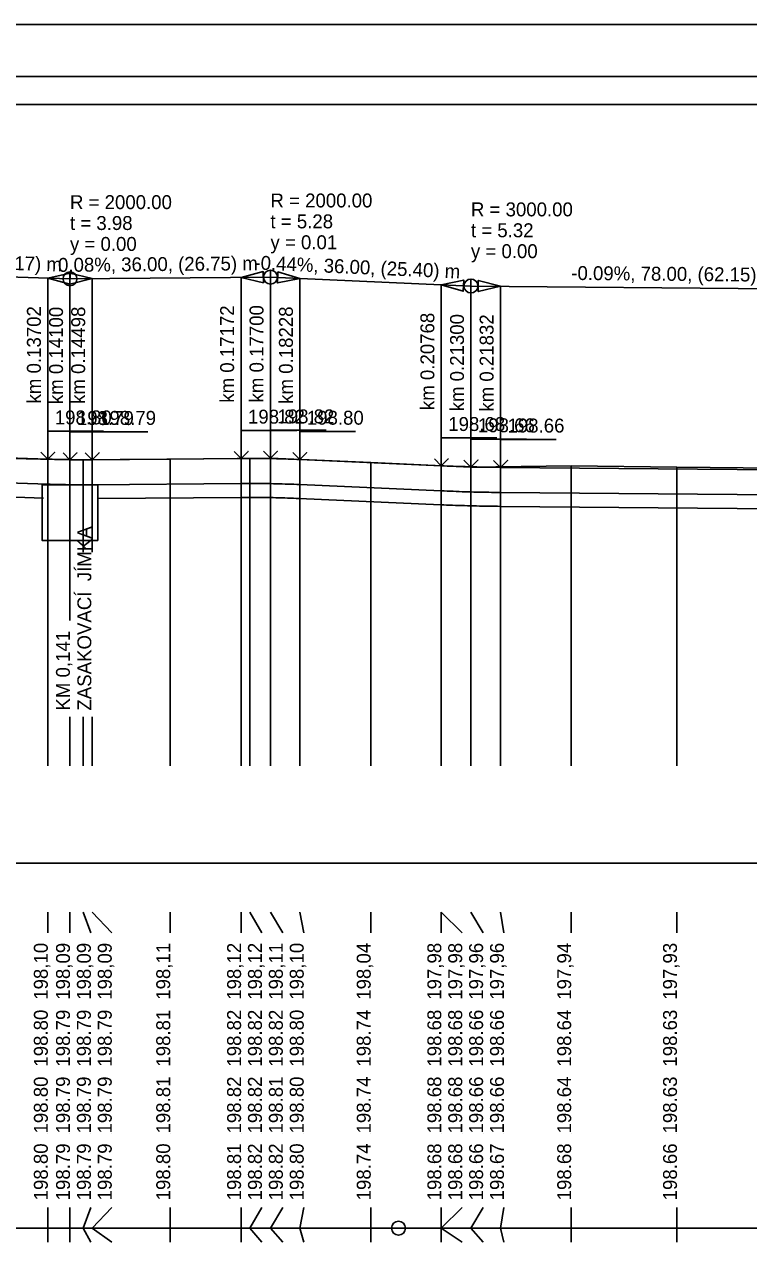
# Model space of a CAD drawing. Extents: x -51 to 53, y -74 to 15.
# Drawn here: x -25.16 to -12.15, y -6.73 to 15.15 of the extents above; entities that cross this region are included whole.
import ezdxf

# ---------------------------------------------------------------- set-up
doc = ezdxf.new("R2010")
doc.units = 0
for name, color, linetype in [('Implicitní', 7, 'Continuous'), ('KONSTRUKCE_L', 7, 'Continuous'), ('KOTY_L', 7, 'Continuous'), ('KOTY_N', 7, 'Continuous'), ('KOTY_S', 7, 'Continuous'), ('KOTY_T', 7, 'Continuous'), ('KOTY_VP', 7, 'Continuous'), ('Nová vrstva (0)', 7, 'Continuous'), ('PR_SKLON_L', 7, 'Continuous'), ('ROVINA_L', 7, 'Continuous'), ('ROVINA_O', 7, 'Continuous'), ('SKLON_POMERY', 7, 'Continuous'), ('TABULKY_L', 7, 'Continuous'), ('TEREN_L', 7, 'Continuous'), ('V_POLYGON', 7, 'Continuous'), ('V_POLYGON_ZO', 7, 'Continuous')]:
    doc.layers.add(name, color=color, linetype=linetype)

msp = doc.modelspace()

# ---------------------------------------------------------------- linework, layer by layer
at = {"layer": 'Implicitní'}
msp.add_lwpolyline([(-51.392, 15.154), (53.079, 15.154), (53.079, -14.546), (-51.392, -14.546)], close=True, dxfattribs=at)
at = {"layer": 'KONSTRUKCE_L'}
for p, q in [((-26.854, 6.968), (-24.738, 6.901)), ((-24.738, 6.901), (-24.698, 6.9)), ((-24.698, 6.9), (-24.658, 6.899)), ((-24.658, 6.899), (-24.618, 6.898)), ((-24.618, 6.898), (-24.579, 6.897)), ((-24.579, 6.897), (-24.539, 6.896)), ((-24.539, 6.896), (-24.499, 6.895)), ((-24.499, 6.895), (-24.459, 6.895)), ((-24.459, 6.895), (-24.42, 6.894)), ((-24.42, 6.894), (-24.38, 6.893)), ((-24.38, 6.893), (-24.34, 6.893)), ((-24.34, 6.893), (-24.3, 6.892)), ((-24.3, 6.892), (-24.26, 6.892)), ((-24.26, 6.892), (-24.221, 6.892)), ((-24.221, 6.892), (-24.181, 6.892)), ((-24.181, 6.892), (-24.141, 6.891)), ((-24.141, 6.891), (-24.101, 6.891)), ((-24.101, 6.891), (-24.062, 6.891)), ((-24.062, 6.891), (-24.022, 6.892)), ((-24.022, 6.892), (-23.982, 6.892)), ((-23.982, 6.892), (-23.942, 6.892)), ((-23.942, 6.892), (-21.268, 6.914)), ((-21.268, 6.914), (-21.215, 6.915)), ((-21.215, 6.915), (-21.162, 6.915)), ((-21.162, 6.915), (-21.109, 6.915)), ((-21.109, 6.915), (-21.057, 6.915)), ((-21.057, 6.915), (-21.004, 6.915)), ((-21.004, 6.915), (-20.951, 6.915)), ((-20.951, 6.915), (-20.898, 6.914)), ((-20.898, 6.914), (-20.846, 6.913)), ((-20.846, 6.913), (-20.793, 6.913)), ((-20.793, 6.913), (-20.74, 6.912)), ((-20.74, 6.912), (-20.687, 6.911)), ((-20.687, 6.911), (-20.634, 6.91)), ((-20.634, 6.91), (-20.582, 6.908)), ((-20.582, 6.908), (-20.529, 6.907)), ((-20.529, 6.907), (-20.476, 6.905)), ((-20.476, 6.905), (-20.423, 6.904)), ((-20.423, 6.904), (-20.371, 6.902)), ((-20.371, 6.902), (-20.318, 6.9)), ((-20.318, 6.9), (-20.265, 6.898)), ((-20.265, 6.898), (-20.212, 6.895)), ((-20.212, 6.895), (-17.672, 6.782)), ((-17.672, 6.782), (-17.619, 6.78)), ((-17.619, 6.78), (-17.566, 6.778)), ((-17.566, 6.778), (-17.512, 6.776)), ((-17.512, 6.776), (-17.459, 6.774)), ((-17.459, 6.774), (-17.406, 6.772)), ((-17.406, 6.772), (-17.353, 6.77)), ((-17.353, 6.77), (-17.3, 6.768)), ((-17.3, 6.768), (-17.246, 6.767)), ((-17.246, 6.767), (-17.193, 6.765)), ((-17.193, 6.765), (-17.14, 6.764)), ((-17.14, 6.764), (-17.087, 6.762)), ((-17.087, 6.762), (-17.034, 6.761)), ((-17.034, 6.761), (-16.98, 6.76)), ((-16.98, 6.76), (-16.927, 6.759)), ((-16.927, 6.759), (-16.874, 6.758)), ((-16.874, 6.758), (-16.821, 6.757)), ((-16.821, 6.757), (-16.768, 6.756)), ((-16.768, 6.756), (-16.714, 6.755)), ((-16.714, 6.755), (-16.661, 6.755)), ((-16.661, 6.755), (-16.608, 6.754)), ((-16.608, 6.754), (-10.393, 6.698))]:
    msp.add_line(p, q, dxfattribs=at)
at = {"layer": 'KOTY_L'}
for p, q in [((-24.738, 1.849), (-24.738, 7.348)), ((-24.34, 4.456), (-24.34, 7.339)), ((-24.101, 5.684), (-24.101, 7.34)), ((-23.942, 5.684), (-23.942, 7.341)), ((-22.54, 1.849), (-22.54, 7.349)), ((-21.268, 1.849), (-21.268, 7.363)), ((-21.109, 1.849), (-21.109, 7.365)), ((-20.74, 1.849), (-20.74, 7.369)), ((-20.212, 1.849), (-20.212, 7.345)), ((-18.94, 1.849), (-18.94, 7.289)), ((-17.672, 1.849), (-17.672, 7.232)), ((-17.672, 1.849), (-17.672, 7.232)), ((-15.34, 1.849), (-15.34, 7.229)), ((-17.14, 1.849), (-17.14, 7.209)), ((-16.608, 1.849), (-16.608, 7.215)), ((-13.44, 1.849), (-13.44, 7.209)), ((-24.34, 1.849), (-24.34, 2.725)), ((-24.101, 1.849), (-24.101, 2.725)), ((-23.942, 1.849), (-23.942, 2.725)), ((-24.738, -1.151), (-24.738, -0.776)), ((-24.34, -1.151), (-24.34, -0.776)), ((-23.965, -1.151), (-24.101, -0.776)), ((-23.59, -1.151), (-23.942, -0.776)), ((-22.54, -1.151), (-22.54, -0.776)), ((-21.268, -1.151), (-21.268, -0.776)), ((-20.893, -1.151), (-21.109, -0.776)), ((-20.518, -1.151), (-20.74, -0.776)), ((-20.143, -1.151), (-20.212, -0.776)), ((-18.94, -1.151), (-18.94, -0.776)), ((-17.672, -1.151), (-17.672, -0.776)), ((-17.297, -1.151), (-17.672, -0.776)), ((-16.922, -1.151), (-17.14, -0.776)), ((-16.547, -1.151), (-16.608, -0.776)), ((-15.34, -1.151), (-15.34, -0.776)), ((-13.44, -1.151), (-13.44, -0.776)), ((-24.738, -4.751), (-24.738, -4.751)), ((-24.34, -4.751), (-24.34, -4.751)), ((-23.965, -4.751), (-23.965, -4.751)), ((-23.59, -4.751), (-23.59, -4.751)), ((-22.54, -4.751), (-22.54, -4.751)), ((-21.268, -4.751), (-21.268, -4.751)), ((-20.893, -4.751), (-20.893, -4.751)), ((-20.518, -4.751), (-20.518, -4.751)), ((-20.143, -4.751), (-20.143, -4.751)), ((-18.94, -4.751), (-18.94, -4.751)), ((-17.672, -4.751), (-17.672, -4.751)), ((-17.297, -4.751), (-17.297, -4.751)), ((-16.922, -4.751), (-16.922, -4.751)), ((-16.547, -4.751), (-16.547, -4.751)), ((-15.34, -4.751), (-15.34, -4.751)), ((-13.44, -4.751), (-13.44, -4.751)), ((-24.738, -6.451), (-24.738, -6.076)), ((-24.34, -6.451), (-24.34, -6.076)), ((-24.101, -6.451), (-23.965, -6.076)), ((-23.942, -6.451), (-23.59, -6.076)), ((-22.54, -6.451), (-22.54, -6.076)), ((-21.268, -6.451), (-21.268, -6.076)), ((-21.109, -6.451), (-20.893, -6.076)), ((-20.74, -6.451), (-20.518, -6.076)), ((-20.212, -6.451), (-20.143, -6.076)), ((-18.94, -6.451), (-18.94, -6.076)), ((-17.672, -6.451), (-17.672, -6.076)), ((-17.672, -6.451), (-17.297, -6.076)), ((-17.14, -6.451), (-16.922, -6.076)), ((-16.608, -6.451), (-16.547, -6.076)), ((-15.34, -6.451), (-15.34, -6.076)), ((-13.44, -6.451), (-13.44, -6.076))]:
    msp.add_line(p, q, dxfattribs=at)
at = {"layer": 'KOTY_S'}
for p, q in [((-24.738, -6.701), (-24.738, -6.451)), ((-24.34, -6.701), (-24.34, -6.451)), ((-23.965, -6.701), (-24.101, -6.451)), ((-23.59, -6.701), (-23.942, -6.451)), ((-22.54, -6.701), (-22.54, -6.451)), ((-21.268, -6.701), (-21.268, -6.451)), ((-20.893, -6.701), (-21.109, -6.451)), ((-20.518, -6.701), (-20.74, -6.451)), ((-20.143, -6.701), (-20.212, -6.451)), ((-18.94, -6.701), (-18.94, -6.451)), ((-17.672, -6.701), (-17.672, -6.451)), ((-17.297, -6.701), (-17.672, -6.451)), ((-16.922, -6.701), (-17.14, -6.451)), ((-16.547, -6.701), (-16.608, -6.451)), ((-15.34, -6.701), (-15.34, -6.451)), ((-13.44, -6.701), (-13.44, -6.451))]:
    msp.add_line(p, q, dxfattribs=at)
at = {"layer": 'Nová vrstva (0)'}
for p, q in [((-26.862, 6.718), (-24.816, 6.654)), ((-23.842, 6.643), (-21.266, 6.664)), ((-21.266, 6.664), (-21.213, 6.665)), ((-21.214, 6.665), (-21.161, 6.665)), ((-21.162, 6.665), (-21.109, 6.665)), ((-21.11, 6.665), (-21.057, 6.665)), ((-21.058, 6.665), (-21.005, 6.665)), ((-21.005, 6.665), (-20.953, 6.665)), ((-20.953, 6.665), (-20.901, 6.664)), ((-20.901, 6.664), (-20.848, 6.663)), ((-20.849, 6.663), (-20.796, 6.663)), ((-20.797, 6.663), (-20.744, 6.662)), ((-20.745, 6.662), (-20.692, 6.661)), ((-20.693, 6.661), (-20.64, 6.66)), ((-20.641, 6.66), (-20.588, 6.658)), ((-20.588, 6.658), (-20.536, 6.657)), ((-20.536, 6.657), (-20.484, 6.655)), ((-20.484, 6.655), (-20.431, 6.654)), ((-20.432, 6.654), (-20.379, 6.652)), ((-20.38, 6.652), (-20.327, 6.65)), ((-20.328, 6.65), (-20.275, 6.648)), ((-20.276, 6.648), (-20.223, 6.646)), ((-20.223, 6.646), (-17.683, 6.533)), ((-17.683, 6.533), (-17.63, 6.53)), ((-17.629, 6.53), (-17.576, 6.528)), ((-17.576, 6.528), (-17.522, 6.526)), ((-17.522, 6.526), (-17.469, 6.524)), ((-17.468, 6.524), (-17.415, 6.522)), ((-17.415, 6.522), (-17.361, 6.52)), ((-17.361, 6.52), (-17.308, 6.518)), ((-17.307, 6.518), (-17.254, 6.517)), ((-17.254, 6.517), (-17.201, 6.515)), ((-17.2, 6.515), (-17.147, 6.514)), ((-17.146, 6.514), (-17.093, 6.512)), ((-17.093, 6.512), (-17.04, 6.511)), ((-17.039, 6.511), (-16.986, 6.51)), ((-16.986, 6.51), (-16.932, 6.509)), ((-16.932, 6.509), (-16.879, 6.508)), ((-16.878, 6.508), (-16.825, 6.507)), ((-16.825, 6.507), (-16.771, 6.506)), ((-16.771, 6.506), (-16.718, 6.505)), ((-16.717, 6.505), (-16.664, 6.505)), ((-16.664, 6.505), (-16.61, 6.504)), ((-16.61, 6.504), (-10.395, 6.448))]:
    msp.add_line(p, q, dxfattribs=at)
msp.add_lwpolyline([(-24.84, 6.892), (-23.84, 6.892), (-23.84, 5.892), (-24.84, 5.892)], close=True, dxfattribs=at)
at = {"layer": 'PR_SKLON_L'}
msp.add_line((-38.44, 0.099), (-11.54, 0.099), dxfattribs=at)
at = {"layer": 'ROVINA_L'}
msp.add_line((-38.44, -6.451), (50.86, -6.451), dxfattribs=at)
at = {"layer": 'ROVINA_O'}
msp.add_circle((-18.44, -6.451), 0.125, dxfattribs=at)
at = {"layer": 'SKLON_POMERY'}
for p, q in [((-20.74, 10.619), (-20.74, 10.744)), ((-27.84, 10.699), (-24.34, 10.589)), ((-24.738, 7.351), (-24.738, 10.601)), ((-24.34, 10.589), (-24.34, 10.714)), ((-24.34, 10.589), (-20.74, 10.619)), ((-24.34, 7.339), (-24.34, 10.589)), ((-23.942, 7.342), (-23.942, 10.592)), ((-21.268, 7.364), (-21.268, 10.614)), ((-20.74, 7.369), (-20.74, 10.619)), ((-20.74, 10.619), (-17.14, 10.459)), ((-20.212, 7.345), (-20.212, 10.595)), ((-17.14, 10.459), (-17.14, 10.584)), ((-17.672, 7.232), (-17.672, 10.482)), ((-17.14, 7.209), (-17.14, 10.459)), ((-17.14, 10.459), (-9.34, 10.389)), ((-16.608, 7.204), (-16.608, 10.454))]:
    msp.add_line(p, q, dxfattribs=at)
for points in [[(-24.738, 10.601), (-24.341, 10.489), (-24.335, 10.689), (-24.738, 10.601)], [(-23.942, 10.592), (-24.342, 10.489), (-24.343, 10.689), (-23.942, 10.592)], [(-21.268, 10.614), (-20.867, 10.518), (-20.869, 10.718), (-21.268, 10.614)], [(-20.212, 10.595), (-20.616, 10.513), (-20.607, 10.713), (-20.212, 10.595)], [(-17.672, 10.482), (-17.277, 10.365), (-17.268, 10.565), (-17.672, 10.482)], [(-16.608, 10.454), (-17.009, 10.358), (-17.007, 10.558), (-16.608, 10.454)]]:
    msp.add_lwpolyline(points, close=True, dxfattribs=at)
for points in [[(-24.863, 7.476), (-24.738, 7.351), (-24.613, 7.476), (-24.738, 7.351), (-24.738, 7.851), (-23.738, 7.851)], [(-24.465, 7.464), (-24.34, 7.339), (-24.215, 7.464), (-24.34, 7.339), (-24.34, 7.839), (-23.34, 7.839)], [(-24.067, 7.467), (-23.942, 7.342), (-23.817, 7.467), (-23.942, 7.342), (-23.942, 7.842), (-22.942, 7.842)], [(-21.393, 7.489), (-21.268, 7.364), (-21.143, 7.489), (-21.268, 7.364), (-21.268, 7.864), (-20.268, 7.864)], [(-20.865, 7.494), (-20.74, 7.369), (-20.615, 7.494), (-20.74, 7.369), (-20.74, 7.869), (-19.74, 7.869)], [(-20.337, 7.47), (-20.212, 7.345), (-20.087, 7.47), (-20.212, 7.345), (-20.212, 7.845), (-19.212, 7.845)], [(-17.797, 7.357), (-17.672, 7.232), (-17.547, 7.357), (-17.672, 7.232), (-17.672, 7.732), (-16.672, 7.732)], [(-17.265, 7.334), (-17.14, 7.209), (-17.015, 7.334), (-17.14, 7.209), (-17.14, 7.709), (-16.14, 7.709)], [(-16.733, 7.329), (-16.608, 7.204), (-16.483, 7.329), (-16.608, 7.204), (-16.608, 7.704), (-15.608, 7.704)]]:
    msp.add_lwpolyline(points, dxfattribs=at)
for centre in [(-20.74, 10.619), (-24.34, 10.589), (-17.14, 10.459)]:
    msp.add_circle(centre, 0.125, dxfattribs=at)
at = {"layer": 'TABULKY_L'}
for p, q in [((-38.44, 14.218), (50.86, 14.218)), ((-38.44, 13.718), (50.86, 13.718))]:
    msp.add_line(p, q, dxfattribs=at)
at = {"layer": 'TEREN_L'}
for p, q in [((-26.14, 7.379), (-24.34, 7.339)), ((-24.34, 7.339), (-22.54, 7.349)), ((-22.54, 7.349), (-20.74, 7.369)), ((-20.74, 7.369), (-18.94, 7.289)), ((-18.94, 7.289), (-17.14, 7.209)), ((-17.14, 7.209), (-15.34, 7.229)), ((-15.34, 7.229), (-13.44, 7.209)), ((-13.44, 7.209), (-11.54, 7.189))]:
    msp.add_line(p, q, dxfattribs=at)
at = {"layer": 'V_POLYGON'}
for p, q in [((-26.854, 7.418), (-24.738, 7.351)), ((-23.942, 7.342), (-21.268, 7.364)), ((-20.212, 7.345), (-17.672, 7.232)), ((-16.608, 7.204), (-10.393, 7.148))]:
    msp.add_line(p, q, dxfattribs=at)
for points in [[(-24.738, 7.351), (-24.698, 7.35), (-24.658, 7.349), (-24.618, 7.348), (-24.579, 7.347), (-24.539, 7.346), (-24.499, 7.345), (-24.459, 7.345), (-24.42, 7.344), (-24.38, 7.343), (-24.34, 7.343), (-24.3, 7.342), (-24.26, 7.342), (-24.221, 7.342), (-24.181, 7.342), (-24.141, 7.341), (-24.101, 7.341), (-24.062, 7.341), (-24.022, 7.342), (-23.982, 7.342), (-23.942, 7.342)], [(-21.268, 7.364), (-21.215, 7.365), (-21.162, 7.365), (-21.109, 7.365), (-21.057, 7.365), (-21.004, 7.365), (-20.951, 7.365), (-20.898, 7.364), (-20.846, 7.363), (-20.793, 7.363), (-20.74, 7.362), (-20.687, 7.361), (-20.634, 7.36), (-20.582, 7.358), (-20.529, 7.357), (-20.476, 7.355), (-20.423, 7.354), (-20.371, 7.352), (-20.318, 7.35), (-20.265, 7.348), (-20.212, 7.345)], [(-17.672, 7.232), (-17.619, 7.23), (-17.566, 7.228), (-17.512, 7.226), (-17.459, 7.224), (-17.406, 7.222), (-17.353, 7.22), (-17.3, 7.218), (-17.246, 7.217), (-17.193, 7.215), (-17.14, 7.214), (-17.087, 7.212), (-17.034, 7.211), (-16.98, 7.21), (-16.927, 7.209), (-16.874, 7.208), (-16.821, 7.207), (-16.768, 7.206), (-16.714, 7.205), (-16.661, 7.205), (-16.608, 7.204)]]:
    msp.add_lwpolyline(points, dxfattribs=at)
at = {"layer": 'V_POLYGON_ZO'}
for p, q in [((-24.738, 7.351), (-24.34, 7.339)), ((-24.34, 7.339), (-23.942, 7.342)), ((-21.268, 7.364), (-20.74, 7.369)), ((-20.74, 7.369), (-20.212, 7.345)), ((-17.672, 7.232), (-17.14, 7.209)), ((-17.14, 7.209), (-16.608, 7.204))]:
    msp.add_line(p, q, dxfattribs=at)

# ---------------------------------------------------------------- texts
at = {"layer": 'KOTY_N'}
for s, p in [('198.80', (-24.738, -4.751)), ('198.79', (-24.34, -4.751)), ('198.79', (-23.965, -4.751)), ('198.79', (-23.59, -4.751)), ('198.81', (-22.54, -4.751)), ('198.82', (-21.268, -4.751)), ('198.82', (-20.893, -4.751)), ('198.81', (-20.518, -4.751)), ('198.80', (-20.143, -4.751)), ('198.74', (-18.94, -4.751)), ('198.68', (-17.672, -4.751)), ('198.68', (-17.297, -4.751)), ('198.66', (-16.922, -4.751)), ('198.66', (-16.547, -4.751)), ('198.64', (-15.34, -4.751)), ('198.63', (-13.44, -4.751))]:
    msp.add_text(s, height=0.25, rotation=90, dxfattribs=at).set_placement(p)
at = {"layer": 'KOTY_T'}
for s, p in [('198.80', (-24.738, -5.951)), ('198.79', (-24.34, -5.951)), ('198.79', (-23.965, -5.951)), ('198.79', (-23.59, -5.951)), ('198.80', (-22.54, -5.951)), ('198.81', (-21.268, -5.951)), ('198.82', (-20.893, -5.951)), ('198.82', (-20.518, -5.951)), ('198.80', (-20.143, -5.951)), ('198.74', (-18.94, -5.951)), ('198.68', (-17.672, -5.951)), ('198.68', (-17.297, -5.951)), ('198.66', (-16.922, -5.951)), ('198.67', (-16.547, -5.951)), ('198.68', (-15.34, -5.951)), ('198.66', (-13.44, -5.951))]:
    msp.add_text(s, height=0.25, rotation=90, dxfattribs=at).set_placement(p)
at = {"layer": 'KOTY_VP'}
for s, p in [('198.80', (-24.738, -3.551)), ('198.79', (-24.34, -3.551)), ('198.79', (-23.965, -3.551)), ('198.79', (-23.59, -3.551)), ('198.81', (-22.54, -3.551)), ('198.82', (-21.268, -3.551)), ('198.82', (-20.893, -3.551)), ('198.82', (-20.518, -3.551)), ('198.80', (-20.143, -3.551)), ('198.74', (-18.94, -3.551)), ('198.68', (-17.672, -3.551)), ('198.68', (-17.297, -3.551)), ('198.66', (-16.922, -3.551)), ('198.66', (-16.547, -3.551)), ('198.64', (-15.34, -3.551)), ('198.63', (-13.44, -3.551))]:
    msp.add_text(s, height=0.25, rotation=90, dxfattribs=at).set_placement(p)
at = {"layer": 'Nová vrstva (0)'}
for s, p in [('ZASAKOVACÍ  JÍMKA', (-23.957, 2.839)), ('KM 0,141', (-24.341, 2.839)), ('198,10', (-24.738, -2.351)), ('198,09', (-24.34, -2.351)), ('198,09', (-23.965, -2.351)), ('198,09', (-23.59, -2.351)), ('198,11', (-22.54, -2.351)), ('198,12', (-21.268, -2.351)), ('198,12', (-20.893, -2.351)), ('198,11', (-20.518, -2.351)), ('198,10', (-20.143, -2.351)), ('198,04', (-18.94, -2.351)), ('197,98', (-17.672, -2.351)), ('197,98', (-17.297, -2.351)), ('197,96', (-16.922, -2.351)), ('197,96', (-16.547, -2.351)), ('197,94', (-15.34, -2.351)), ('197,93', (-13.44, -2.351))]:
    msp.add_text(s, height=0.25, rotation=90, dxfattribs=at).set_placement(p)
at = {"layer": 'SKLON_POMERY'}
for s, p in [('R = 2000.00', (-24.34, 11.839)), ('R = 2000.00', (-20.74, 11.869)), ('R = 3000.00', (-17.14, 11.709)), ('t = 3.98', (-24.34, 11.464)), ('t = 5.28', (-20.74, 11.494)), ('t = 5.32', (-17.14, 11.334)), ('y = 0.00', (-24.34, 11.089)), ('y = 0.01', (-20.74, 11.119)), ('y = 0.00', (-17.14, 10.959)), ('198.80', (-24.613, 7.976)), ('198.79', (-24.215, 7.964)), ('198.79', (-23.817, 7.967)), ('198.82', (-21.143, 7.989)), ('198.82', (-20.615, 7.994)), ('198.80', (-20.087, 7.97)), ('198.68', (-17.547, 7.857)), ('198.66', (-17.015, 7.834)), ('198.66', (-16.483, 7.829))]:
    msp.add_text(s, height=0.25, dxfattribs=at).set_placement(p)
for s, rotation, p in [('-0.31%, 35.00, (21.17) m', 358.1999, (-28.185, 10.835)), ('0.08%, 36.00, (26.75) m', 0.4774, (-24.553, 10.712)), ('-0.44%, 36.00, (25.40) m', 357.4552, (-21.032, 10.757)), ('-0.09%, 78.00, (62.15) m', 359.4858, (-15.339, 10.568)), ('km 0.13702', 90, (-24.863, 8.351)), ('km 0.14100', 90, (-24.465, 8.339)), ('km 0.14498', 90, (-24.067, 8.342)), ('km 0.17172', 90, (-21.393, 8.364)), ('km 0.17700', 90, (-20.865, 8.369)), ('km 0.18228', 90, (-20.337, 8.345)), ('km 0.20768', 90, (-17.797, 8.232)), ('km 0.21300', 90, (-17.265, 8.209)), ('km 0.21832', 90, (-16.733, 8.204))]:
    msp.add_text(s, height=0.25, rotation=rotation, dxfattribs=at).set_placement(p)

doc.saveas('drawing.dxf')
